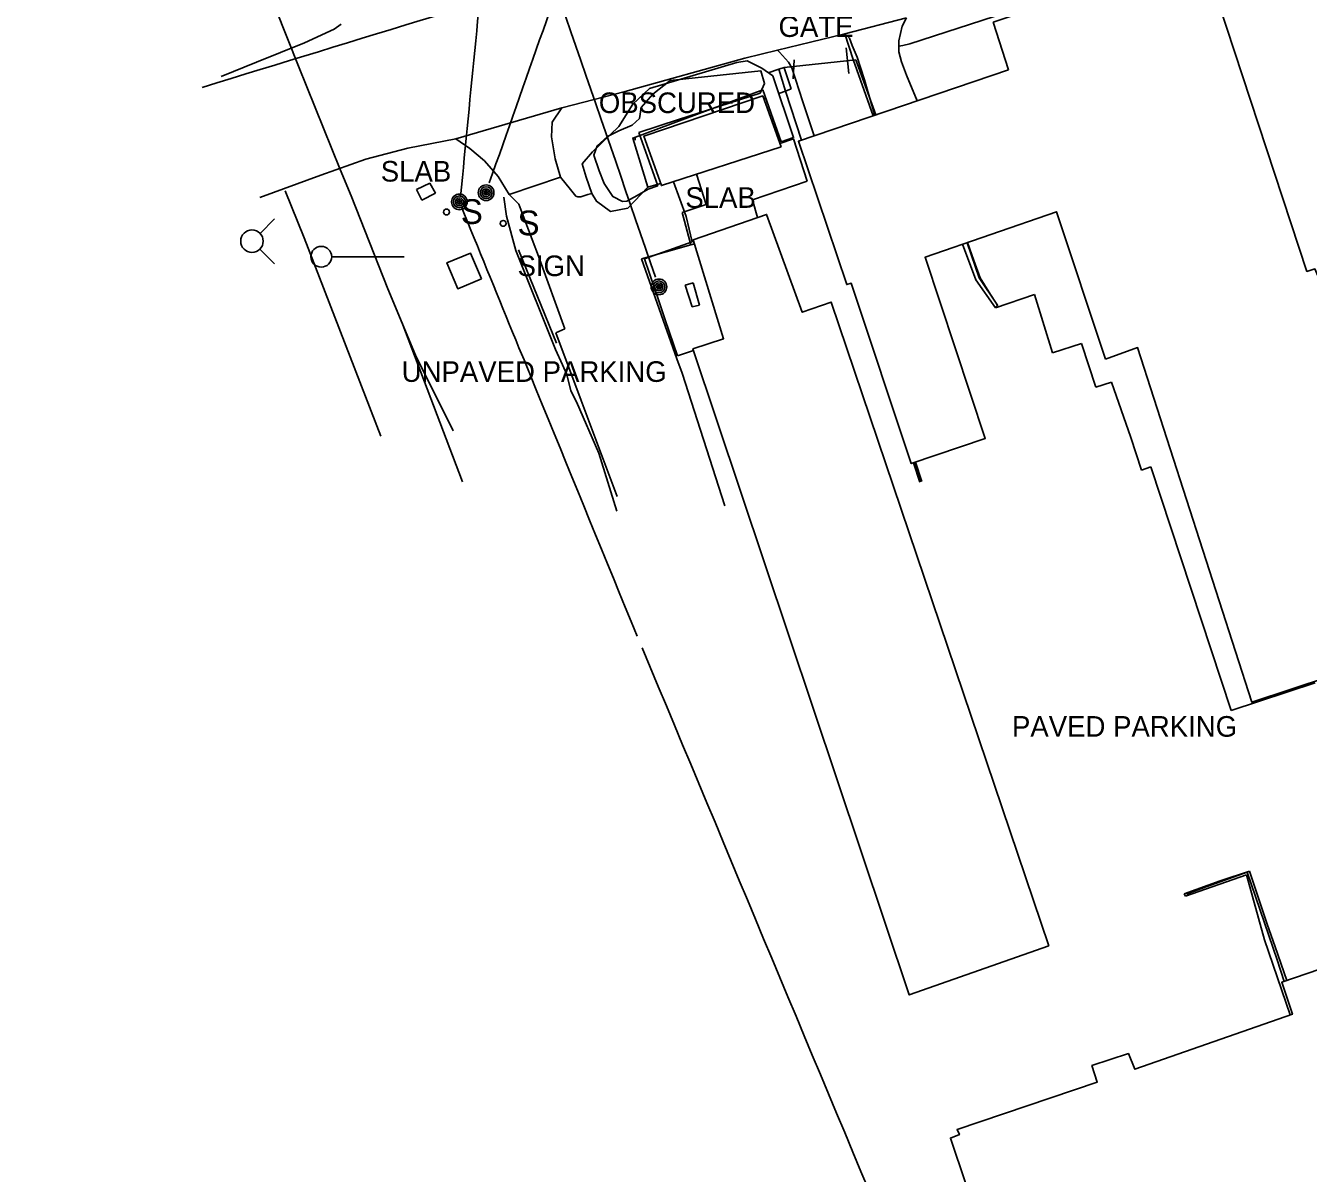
# Model space of a CAD drawing. Extents: x 368532 to 392481, y 10654822 to 10676899.
# Drawn here: x 378002.7 to 378313.7, y 10661264.3 to 10661542.7 of the extents above; entities that cross this region are included whole.
import ezdxf

# ---------------------------------------------------------------- set-up
doc = ezdxf.new("R2010")
doc.units = 0
for name, color, linetype in [('p_Catenary', 7, 'Continuous'), ('p_dtm obscured area', 7, 'Continuous'), ('p_dtm retaining wall', 7, 'Continuous'), ('p_dtm sidewalk', 7, 'Continuous'), ('p_dtm slab', 7, 'Continuous'), ('p_railroad rr control', 7, 'Continuous'), ('p_road - paved curb', 7, 'Continuous'), ('p_road general road feature', 7, 'Continuous'), ('p_structure building', 7, 'Continuous'), ('p_structure fence', 7, 'Continuous'), ('p_structure sign', 7, 'Continuous'), ('p_structure tank', 7, 'Continuous'), ('p_utility general pole', 7, 'Continuous'), ('p_veg woods', 7, 'Continuous')]:
    doc.layers.add(name, color=color, linetype=linetype)

msp = doc.modelspace()

# ---------------------------------------------------------------- linework, layer by layer
at = {"layer": 'p_Catenary'}
for points in [[(378045.46, 10661527.75), (378048.98, 10661528.83), (378052.51, 10661529.92), (378056.03, 10661531), (378059.56, 10661532.08), (378063.09, 10661533.16), (378066.61, 10661534.24), (378070.14, 10661535.32), (378073.66, 10661536.4), (378077.19, 10661537.49), (378080.71, 10661538.57), (378084.24, 10661539.65), (378087.77, 10661540.73), (378091.29, 10661541.81), (378094.82, 10661542.89), (378098.34, 10661543.97), (378101.87, 10661545.06), (378105.39, 10661546.14), (378108.92, 10661547.22), (378112.45, 10661548.3)], [(378115.09, 10661504.56), (378115.91, 10661506.88), (378116.72, 10661509.19), (378117.54, 10661511.5), (378118.35, 10661513.82), (378119.17, 10661516.13), (378119.98, 10661518.44), (378120.8, 10661520.75), (378121.61, 10661523.07), (378122.42, 10661525.38), (378123.24, 10661527.69), (378124.05, 10661530.01), (378124.87, 10661532.32), (378125.68, 10661534.63), (378126.5, 10661536.95), (378127.31, 10661539.26), (378128.13, 10661541.57), (378128.94, 10661543.88), (378129.76, 10661546.2), (378130.57, 10661548.51)], [(378132.49, 10661548.25), (378133.69, 10661544.75), (378134.9, 10661541.25), (378136.11, 10661537.74), (378137.31, 10661534.24), (378138.52, 10661530.74), (378139.73, 10661527.24), (378140.93, 10661523.74), (378142.14, 10661520.24), (378143.35, 10661516.74), (378144.55, 10661513.23), (378145.76, 10661509.73), (378146.97, 10661506.23), (378148.17, 10661502.73), (378149.38, 10661499.23), (378150.59, 10661495.73), (378151.79, 10661492.23), (378153, 10661488.72), (378154.21, 10661485.22), (378155.41, 10661481.72)], [(378112.51, 10661546.16), (378112.27, 10661543.8), (378112.04, 10661541.43), (378111.81, 10661539.06), (378111.58, 10661536.69), (378111.35, 10661534.33), (378111.12, 10661531.96), (378110.89, 10661529.59), (378110.66, 10661527.22), (378110.42, 10661524.85), (378110.19, 10661522.49), (378109.96, 10661520.12), (378109.73, 10661517.75), (378109.5, 10661515.38), (378109.27, 10661513.02), (378109.04, 10661510.65), (378108.81, 10661508.28), (378108.57, 10661505.91), (378108.34, 10661503.54), (378108.11, 10661501.18)], [(378108.33, 10661498.81), (378109.1, 10661496.91), (378109.88, 10661495.01), (378110.66, 10661493.11), (378111.43, 10661491.2), (378112.21, 10661489.3), (378112.98, 10661487.4), (378113.76, 10661485.5), (378114.53, 10661483.6), (378115.31, 10661481.7), (378116.08, 10661479.8), (378116.86, 10661477.9), (378117.63, 10661476), (378118.41, 10661474.1), (378119.19, 10661472.2), (378119.96, 10661470.3), (378120.74, 10661468.4), (378121.51, 10661466.5), (378122.29, 10661464.6), (378123.92, 10661460.9)], [(378150.94, 10661394.65), (378149.5, 10661398.16), (378148.06, 10661401.67), (378146.62, 10661405.19), (378145.19, 10661408.7), (378143.75, 10661412.21), (378142.31, 10661415.73), (378140.88, 10661419.24), (378139.44, 10661422.75), (378138, 10661426.27), (378136.56, 10661429.78), (378135.13, 10661433.29), (378133.69, 10661436.8), (378132.25, 10661440.32), (378130.82, 10661443.83), (378129.38, 10661447.34), (378127.94, 10661450.86), (378126.5, 10661454.37), (378125.07, 10661457.88), (378123.63, 10661461.4)], [(378152.15, 10661391.83), (378154.12, 10661387.13), (378156.08, 10661382.42), (378158.05, 10661377.71), (378160.01, 10661373.01), (378161.98, 10661368.3), (378163.95, 10661363.6), (378165.91, 10661358.89), (378167.88, 10661354.19), (378169.85, 10661349.48), (378171.81, 10661344.78), (378173.78, 10661340.07), (378175.74, 10661335.37), (378177.71, 10661330.66), (378179.68, 10661325.96), (378181.64, 10661321.25), (378183.61, 10661316.54), (378185.57, 10661311.84), (378187.54, 10661307.13), (378189.51, 10661302.43), (378191.47, 10661297.72), (378193.44, 10661293.02), (378195.41, 10661288.31), (378197.37, 10661283.61), (378199.34, 10661278.9), (378201.3, 10661274.2), (378203.27, 10661269.49), (378205.24, 10661264.79), (378207.2, 10661260.08)]]:
    msp.add_lwpolyline(points, dxfattribs=at)
at = {"layer": 'p_dtm obscured area'}
for points in [[(378181.47, 10661527.19), (378149.91, 10661515.44), (378153.55, 10661503.55), (378148.68, 10661498.45), (378144.48, 10661497.62), (378141.11, 10661500.12), (378139.96, 10661502), (378138.59, 10661505.98), (378137.65, 10661509.23), (378140.13, 10661512.09), (378146.49, 10661518.25), (378149.94, 10661523.7), (378153.97, 10661527.46), (378175.13, 10661533.81), (378177.63, 10661534.22), (378181.23, 10661532.37), (378183.87, 10661530.54), (378188.92, 10661515.57), (378185.87, 10661514.52)], [(378185.87, 10661514.52), (378181.47, 10661527.19)]]:
    msp.add_lwpolyline(points, dxfattribs=at)
at = {"layer": 'p_dtm retaining wall'}
for p, q in [((378233.95, 10661481.58), (378230.99, 10661490.08)), ((378238.33, 10661474.94), (378233.95, 10661481.58)), ((378237.85, 10661474.27), (378238.33, 10661474.94)), ((378298.9, 10661337.38), (378288.99, 10661333.81)), ((378306.18, 10661316.08), (378298.9, 10661337.38)), ((378288.99, 10661333.81), (378284.16, 10661332.01)), ((378307.87, 10661310.86), (378306.18, 10661316.08))]:
    msp.add_line(p, q, dxfattribs=at)
at = {"layer": 'p_dtm sidewalk'}
for p, q in [((378276.47, 10661557.61), (378217.08, 10661538.32)), ((378215.41, 10661537.94), (378214.41, 10661537.76)), ((378217.08, 10661538.32), (378215.41, 10661537.94))]:
    msp.add_line(p, q, dxfattribs=at)
at = {"layer": 'p_dtm slab'}
for p, q in [((378185.6, 10661514.12), (378188.9, 10661515.28)), ((378188.9, 10661515.28), (378192.23, 10661505)), ((378097.43, 10661502.96), (378100.7, 10661504.54)), ((378100.7, 10661504.54), (378102.05, 10661502.07)), ((378167.67, 10661499.34), (378165.32, 10661506.68)), ((378192.23, 10661505), (378178.97, 10661500.46)), ((378098.72, 10661500.4), (378097.43, 10661502.96)), ((378102.05, 10661502.07), (378098.72, 10661500.4)), ((378161.84, 10661497.41), (378167.67, 10661499.34)), ((378178.97, 10661500.46), (378180.15, 10661496.18)), ((378163.95, 10661489.56), (378161.84, 10661497.41)), ((378164.86, 10661489.82), (378163.95, 10661489.56))]:
    msp.add_line(p, q, dxfattribs=at)
at = {"layer": 'p_railroad rr control'}
for p, q in [((378059.49, 10661492.33), (378062.99, 10661495.85)), ((378059.46, 10661488.5), (378062.99, 10661484.98)), ((378094.43, 10661486.65), (378076.85, 10661486.65))]:
    msp.add_line(p, q, dxfattribs=at)
for points in [[(378106.34, 10661444.45), (378097.24, 10661462.79), (378090.48, 10661478.85), (378081.61, 10661501.46), (378078.92, 10661507.79), (378068.82, 10661532.9), (378060.51, 10661553.93), (378050.49, 10661579.36), (378038.64, 10661611.01), (378029.14, 10661636.43), (378019.47, 10661662.44), (378010.17, 10661687.96), (378002.65, 10661708.42)], [(378088.76, 10661443.18), (378070.16, 10661491.23), (378065.62, 10661502.68)], [(378108.59, 10661432.05), (378093.86, 10661470.82)]]:
    msp.add_lwpolyline(points, dxfattribs=at)
for centre, radius in [((378057.54, 10661490.44), 2.73), ((378074.35, 10661486.67), 2.52)]:
    msp.add_circle(centre, radius, dxfattribs=at)
at = {"layer": 'p_road - paved curb'}
for p, q in [((378077.51, 10661541.85), (378070.32, 10661538.58)), ((378079.14, 10661543.11), (378077.51, 10661541.85)), ((378201.36, 10661540.76), (378216.32, 10661544.6)), ((378058.65, 10661533.85), (378070.32, 10661538.58)), ((378184.98, 10661536.74), (378192.99, 10661538.68)), ((378192.99, 10661538.68), (378201.36, 10661540.76)), ((378177.08, 10661534.86), (378184.98, 10661536.74)), ((378050.1, 10661530.4), (378058.65, 10661533.85)), ((378148.06, 10661526.76), (378177.08, 10661534.86)), ((378132.66, 10661522.75), (378148.06, 10661526.76)), ((378106.99, 10661515.27), (378132.66, 10661522.75)), ((378095.38, 10661512.97), (378106.99, 10661515.27)), ((378085.16, 10661510.34), (378095.38, 10661512.97)), ((378074.22, 10661506.45), (378085.16, 10661510.34)), ((378059.44, 10661501.06), (378074.22, 10661506.45))]:
    msp.add_line(p, q, dxfattribs=at)
at = {"layer": 'p_road general road feature'}
for p, q in [((378214.4, 10661539.07), (378215.21, 10661542.56)), ((378215.21, 10661542.56), (378216.32, 10661544.6)), ((378203.39, 10661534.49), (378201.36, 10661540.76)), ((378201.36, 10661540.76), (378202.44, 10661539.68)), ((378202.44, 10661539.68), (378203.11, 10661537.9)), ((378214.41, 10661537.76), (378214.4, 10661539.07)), ((378185.5, 10661536.26), (378184.98, 10661536.74)), ((378185.5, 10661536.26), (378187.68, 10661533.86)), ((378203.11, 10661537.9), (378204.31, 10661535.09)), ((378214.41, 10661536.34), (378214.41, 10661537.76)), ((378215.07, 10661533.91), (378214.41, 10661536.34)), ((378187.68, 10661533.86), (378188.48, 10661532.48)), ((378188.48, 10661532.48), (378191.17, 10661524.21)), ((378208.22, 10661520.85), (378203.39, 10661534.49)), ((378204.31, 10661535.09), (378206.1, 10661529.54)), ((378216.29, 10661530.74), (378215.07, 10661533.91)), ((378206.1, 10661529.54), (378207.77, 10661523.67)), ((378218.88, 10661524.47), (378216.29, 10661530.74)), ((378191.17, 10661524.21), (378193.87, 10661515.98)), ((378207.77, 10661523.67), (378208.61, 10661520.99)), ((378132.66, 10661522.75), (378130.32, 10661519.34)), ((378130.32, 10661519.34), (378130.17, 10661515.72)), ((378110.4, 10661512.91), (378106.99, 10661515.27)), ((378130.17, 10661515.72), (378131.1, 10661510.43)), ((378113.95, 10661509.97), (378110.4, 10661512.91)), ((378117.23, 10661506.1), (378113.95, 10661509.97)), ((378131.1, 10661510.43), (378132.38, 10661505.99)), ((378117.23, 10661506.1), (378119.89, 10661501.78)), ((378132.38, 10661505.99), (378119.89, 10661501.78)), ((378132.38, 10661505.99), (378134.76, 10661502.97)), ((378153.55, 10661503.55), (378156.66, 10661504.45)), ((378122.25, 10661499.43), (378119.89, 10661501.78)), ((378134.76, 10661502.97), (378136.05, 10661501.37)), ((378136.05, 10661501.37), (378136.56, 10661501.19)), ((378137.32, 10661501.18), (378139.02, 10661501.73)), ((378139.02, 10661501.73), (378139.96, 10661502)), ((378124, 10661494.87), (378122.25, 10661499.43)), ((378136.56, 10661501.19), (378137.32, 10661501.18)), ((378127.02, 10661486.79), (378124, 10661494.87)), ((378163.95, 10661489.56), (378152, 10661486.18)), ((378233.11, 10661481.07), (378229.87, 10661489.69)), ((378133.4, 10661469.17), (378127.02, 10661486.79)), ((378152, 10661486.18), (378160.55, 10661461.92)), ((378237.85, 10661474.27), (378233.11, 10661481.07)), ((378247.35, 10661477.51), (378237.85, 10661474.27)), ((378251.72, 10661463.36), (378247.35, 10661477.51)), ((378131.27, 10661468.23), (378133.4, 10661469.17)), ((378137.39, 10661451.83), (378131.27, 10661468.23)), ((378258.72, 10661465.61), (378251.72, 10661463.36)), ((378262.24, 10661455), (378258.72, 10661465.61)), ((378160.55, 10661461.92), (378161.85, 10661458.42)), ((378161.85, 10661458.42), (378172.24, 10661426.27)), ((378266.03, 10661456.23), (378262.24, 10661455)), ((378270.69, 10661442.78), (378266.03, 10661456.23)), ((378146.11, 10661428.53), (378137.39, 10661451.83)), ((378273.28, 10661434.86), (378270.69, 10661442.78)), ((378217.98, 10661436.67), (378219.54, 10661431.96)), ((378218.31, 10661436.79), (378219.87, 10661432.07)), ((378218.45, 10661436.83), (378220.01, 10661432.12)), ((378275.51, 10661435.71), (378273.28, 10661434.86)), ((378295.06, 10661376.59), (378275.51, 10661435.71)), ((378315.39, 10661383.27), (378295.06, 10661376.59)), ((378283.94, 10661331.55), (378298.76, 10661336.72)), ((378299.45, 10661337.63), (378292.37, 10661335.24)), ((378298.76, 10661336.72), (378303.14, 10661320.98)), ((378303.8, 10661324.76), (378299.45, 10661337.63)), ((378292.37, 10661335.24), (378283.67, 10661332.11)), ((378283.67, 10661332.11), (378283.94, 10661331.55)), ((378305.67, 10661319.25), (378303.8, 10661324.76)), ((378303.14, 10661320.98), (378309.37, 10661302.74)), ((378308.5, 10661311.07), (378305.67, 10661319.25))]:
    msp.add_line(p, q, dxfattribs=at)
at = {"layer": 'p_structure building'}
for points in [[(378237.31, 10661543.53), (378288.02, 10661560.4), (378313.39, 10661483.09), (378315.33, 10661483.71), (378322.42, 10661467.03), (378322.54, 10661466.53), (378346.74, 10661394.1), (378300.07, 10661378.61), (378272.34, 10661464.63), (378264.56, 10661461.79)], [(378241.04, 10661532), (378237.31, 10661543.53)], [(378264.56, 10661461.79), (378252.65, 10661497.6), (378220.81, 10661486.55), (378235.39, 10661442.55), (378217.42, 10661436.48), (378202.9, 10661480.25), (378201.8, 10661479.93), (378190.08, 10661514.69), (378241.04, 10661532)]]:
    msp.add_lwpolyline(points, dxfattribs=at)
for points in [[(378185.88, 10661513.36), (378181.41, 10661525.67), (378152.6, 10661515.92), (378156.85, 10661503.92)], [(378250.79, 10661319.51), (378216.95, 10661307.6), (378164.48, 10661464.32), (378171.91, 10661466.77), (378164.56, 10661490.78), (378182.37, 10661496.95), (378191.02, 10661473.22), (378198.02, 10661475.65)], [(378113.2, 10661481.3), (378107.44, 10661478.9), (378104.83, 10661485.22), (378110.55, 10661487.51)], [(378392.88, 10661330.36), (378423.53, 10661239.14), (378325.28, 10661206.29), (378322.09, 10661212.63), (378266.19, 10661193.97), (378259.04, 10661214.31), (378251.16, 10661211.57), (378247.21, 10661222.42), (378246.32, 10661222.16), (378244, 10661228.62), (378242.1, 10661227.82), (378226.95, 10661272.86), (378229.12, 10661273.73), (378228.57, 10661274.97), (378262.56, 10661286.41), (378261.27, 10661290.47), (378270.12, 10661293.39), (378271.68, 10661289.56), (378309.9, 10661302.93), (378307.31, 10661310.67), (378338.08, 10661321.18), (378340.96, 10661313.58)]]:
    msp.add_lwpolyline(points, close=True, dxfattribs=at)
at = {"layer": 'p_structure fence'}
for p, q in [((378202.28, 10661531.11), (378201.67, 10661537.32)), ((378186.58, 10661532.57), (378185.36, 10661532.14)), ((378204.01, 10661534.47), (378186.58, 10661532.57)), ((378186.61, 10661532.52), (378188.33, 10661527.43)), ((378188.81, 10661529.79), (378189.05, 10661534.42)), ((378208.88, 10661521.08), (378204.01, 10661534.47)), ((378185.36, 10661532.14), (378182.75, 10661531.31)), ((378185.36, 10661532.14), (378186.98, 10661526.83)), ((378186.98, 10661526.83), (378185.31, 10661526.26)), ((378188.32, 10661527.42), (378186.98, 10661526.83)), ((378186.98, 10661526.83), (378190.81, 10661514.94)), ((378182.17, 10661525.17), (378181.66, 10661524.99)), ((378150.45, 10661515.64), (378150.45, 10661514.93)), ((378162.85, 10661496.43), (378159.75, 10661504.87)), ((378119.28, 10661496.48), (378118.64, 10661501.1)), ((378121.55, 10661488.2), (378119.28, 10661496.48)), ((378164.34, 10661490.25), (378162.85, 10661496.43)), ((378152.76, 10661486.2), (378164.34, 10661490.25)), ((378232.64, 10661485.73), (378231.08, 10661490.11)), ((378131.19, 10661464.14), (378121.55, 10661488.2)), ((378156.42, 10661475.51), (378152.76, 10661486.2)), ((378234.14, 10661481.56), (378232.64, 10661485.73)), ((378236.25, 10661478.18), (378234.14, 10661481.56)), ((378238.42, 10661474.76), (378236.25, 10661478.18)), ((378157.78, 10661471.35), (378156.42, 10661475.51)), ((378160.75, 10661462.61), (378157.78, 10661471.35)), ((378132.82, 10661460.45), (378131.19, 10661464.14)), ((378164.61, 10661463.9), (378160.75, 10661462.61)), ((378133.92, 10661458.14), (378132.82, 10661460.45)), ((378134.84, 10661454.16), (378133.92, 10661458.14)), ((378136.23, 10661451.49), (378134.84, 10661454.16)), ((378141.7, 10661439.04), (378136.23, 10661451.49)), ((378146.07, 10661424.97), (378141.7, 10661439.04))]:
    msp.add_line(p, q, dxfattribs=at)
at = {"layer": 'p_structure sign'}
msp.add_lwpolyline([(378122.17, 10661488.31), (378131.4, 10661465.7)], dxfattribs=at)
for centre in [(378104.72, 10661497.52), (378118.48, 10661494.76)]:
    msp.add_circle(centre, 0.713, dxfattribs=at)
at = {"layer": 'p_structure tank'}
for p, q in [((378162.59, 10661479.79), (378164.55, 10661480.33)), ((378164.31, 10661474.48), (378162.59, 10661479.79)), ((378164.55, 10661480.33), (378166.1, 10661474.95)), ((378166.1, 10661474.95), (378164.31, 10661474.48))]:
    msp.add_line(p, q, dxfattribs=at)
at = {"layer": 'p_utility general pole'}
for centre, radius in [((378107.86, 10661499.98), 1.9), ((378107.86, 10661499.98), 1.44), ((378114.34, 10661502.2), 1.9), ((378114.34, 10661502.2), 1.44), ((378114.34, 10661502.2), 0.973), ((378114.34, 10661502.2), 0.539), ((378114.34, 10661502.2), 0.192), ((378107.86, 10661499.98), 0.973), ((378107.86, 10661499.98), 0.539), ((378107.86, 10661499.98), 0.192), ((378156.25, 10661479.36), 1.9), ((378156.25, 10661479.36), 1.44), ((378156.25, 10661479.36), 0.973), ((378156.25, 10661479.36), 0.539), ((378156.25, 10661479.36), 0.192)]:
    msp.add_circle(centre, radius, dxfattribs=at)
at = {"layer": 'p_veg woods'}
for points in [[(378155.94, 10661503.86), (378153.67, 10661503.07), (378150.99, 10661501.5), (378148.43, 10661500.12), (378147.37, 10661500.03), (378145.04, 10661501.28), (378142.98, 10661504.44), (378141.75, 10661507.5), (378140.48, 10661511.3), (378141.26, 10661513.58), (378143.77, 10661515.82), (378146.5, 10661517.19), (378149.75, 10661518.61), (378151.52, 10661520.24), (378151.91, 10661522.89), (378154.76, 10661526.08), (378158.97, 10661529.41), (378180.92, 10661531.78), (378181.86, 10661528.69), (378180.78, 10661526.37)], [(378161.02, 10661519.97), (378180.78, 10661526.37)], [(378161.02, 10661519.97), (378151.35, 10661516.84)], [(378155.94, 10661503.86), (378151.35, 10661516.84)]]:
    msp.add_lwpolyline(points, dxfattribs=at)

# ---------------------------------------------------------------- texts
at = {"layer": 'p_dtm obscured area'}
msp.add_text(' OBSCURED', height=5, dxfattribs=at).set_placement((378139.81, 10661521.52))
at = {"layer": 'p_dtm slab'}
for p in [(378086.92, 10661504.9), (378160.79, 10661498.53)]:
    msp.add_text(' SLAB', height=5, dxfattribs=at).set_placement(p)
at = {"layer": 'p_road general road feature'}
for s, p in [(' UNPAVED PARKING', (378091.99, 10661456.31)), (' PAVED PARKING', (378240.01, 10661370.24))]:
    msp.add_text(s, height=5, dxfattribs=at).set_placement(p)
at = {"layer": 'p_structure fence'}
msp.add_text(' GATE', height=5, dxfattribs=at).set_placement((378183.39, 10661539.99))
at = {"layer": 'p_structure sign'}
for s, height, p in [('S', 6, (378108.18, 10661494.62)), ('S', 6, (378121.94, 10661491.87)), (' SIGN', 5, (378120.09, 10661481.97))]:
    msp.add_text(s, height=height, dxfattribs=at).set_placement(p)

doc.saveas('drawing.dxf')
